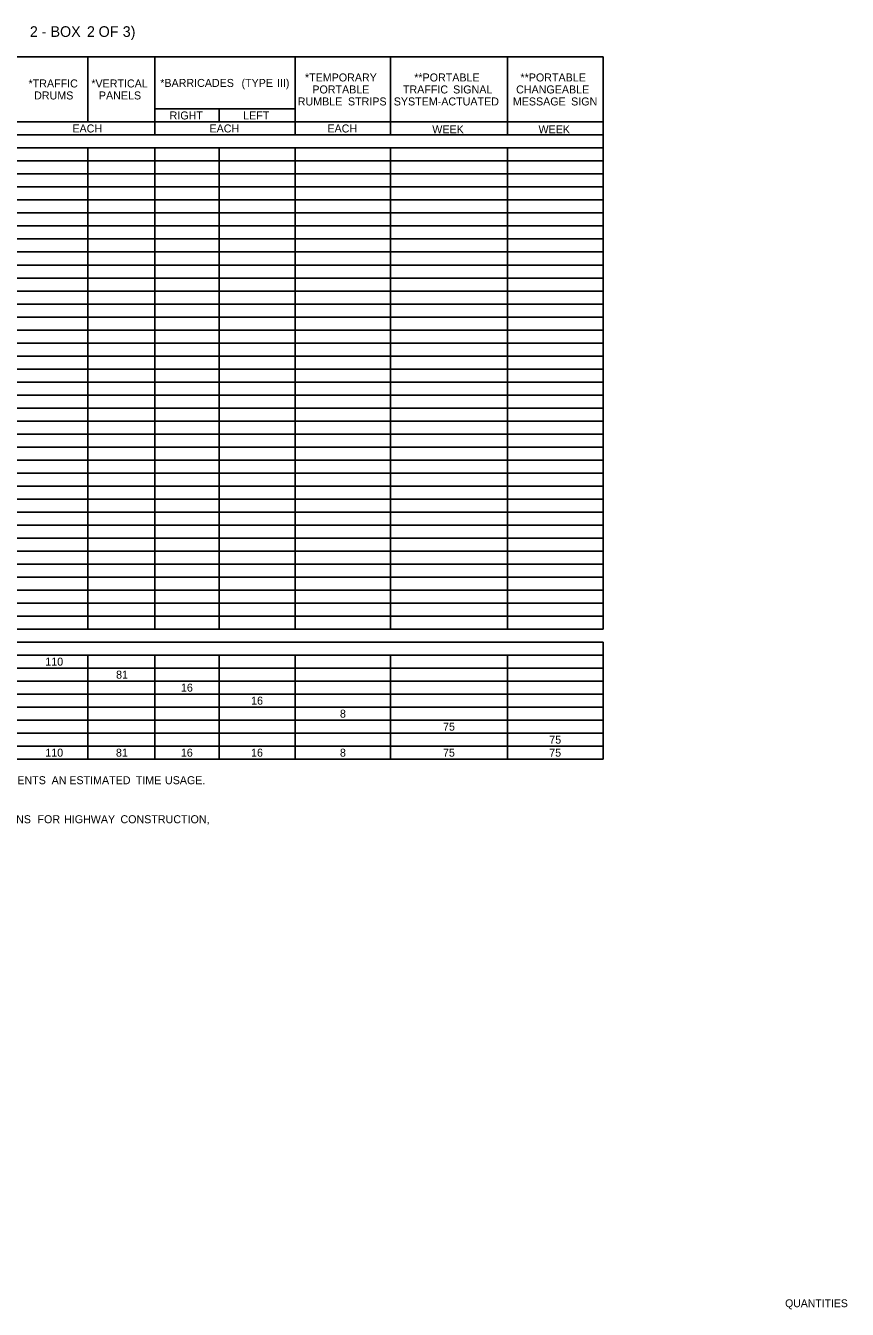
# Model space of a CAD drawing. Extents: x 542596 to 1930787, y -1948294 to 596640.
# Drawn here: x 546993 to 547610, y -1946064 to -1945102 of the extents above; entities that cross this region are included whole.
import ezdxf

# ---------------------------------------------------------------- set-up
doc = ezdxf.new("R2010")
doc.units = 0
doc.layers.add('Default', color=7, linetype='Continuous')
doc.layers.add('R_Border Prem', color=7, linetype='Continuous')

msp = doc.modelspace()

# ---------------------------------------------------------------- linework, layer by layer
at = {"layer": 'Default'}
for p, q in [((546362.8, -1945125.02), (547426.53, -1945125.02)), ((547039.94, -1945173.77), (547039.94, -1945125.02)), ((547090.15, -1945173.77), (547090.15, -1945125.02)), ((547090.15, -1945183.52), (547090.15, -1945125.02)), ((547195.45, -1945183.52), (547195.45, -1945125.02)), ((547267.12, -1945183.52), (547267.12, -1945125.02)), ((547354.87, -1945183.52), (547354.87, -1945125.02)), ((547426.53, -1945554.02), (547426.53, -1945125.02)), ((547090.15, -1945164.02), (547195.45, -1945164.02)), ((547138.42, -1945173.77), (547138.42, -1945164.02)), ((547138.42, -1945173.77), (547138.42, -1945164.02)), ((546889.3, -1945173.77), (547426.53, -1945173.77)), ((547090.15, -1945173.77), (547138.42, -1945173.77)), ((547138.42, -1945173.77), (547426.53, -1945173.77)), ((547195.45, -1945183.52), (547195.45, -1945173.77)), ((547267.12, -1945183.52), (547267.12, -1945173.77)), ((547354.87, -1945183.52), (547354.87, -1945173.77)), ((546362.8, -1945183.52), (547426.53, -1945183.52)), ((546831.29, -1945183.52), (547426.53, -1945183.52)), ((546362.8, -1945193.27), (547426.53, -1945193.27)), ((547039.94, -1945534.52), (547039.94, -1945193.27)), ((547039.94, -1945554.02), (547039.94, -1945193.27)), ((547090.15, -1945534.52), (547090.15, -1945193.27)), ((547090.15, -1945554.02), (547090.15, -1945193.27)), ((547138.42, -1945534.52), (547138.42, -1945193.27)), ((547138.42, -1945554.02), (547138.42, -1945193.27)), ((547195.45, -1945534.52), (547195.45, -1945193.27)), ((547195.45, -1945554.02), (547195.45, -1945193.27)), ((547267.12, -1945554.02), (547267.12, -1945193.27)), ((547354.87, -1945554.02), (547354.87, -1945193.27)), ((546362.8, -1945203.02), (547426.53, -1945203.02)), ((546362.8, -1945212.77), (547426.53, -1945212.77)), ((546362.8, -1945222.52), (547426.53, -1945222.52)), ((546362.8, -1945232.27), (547426.53, -1945232.27)), ((546362.8, -1945242.02), (547426.53, -1945242.02)), ((546362.8, -1945251.77), (547426.53, -1945251.77)), ((546362.8, -1945261.52), (547426.53, -1945261.52)), ((546362.8, -1945271.27), (547426.53, -1945271.27)), ((546362.8, -1945281.02), (547426.53, -1945281.02)), ((546362.8, -1945290.77), (547426.53, -1945290.77)), ((546362.8, -1945300.52), (547426.53, -1945300.52)), ((546362.8, -1945310.27), (547426.53, -1945310.27)), ((546362.8, -1945320.02), (547426.53, -1945320.02)), ((546362.8, -1945329.77), (547426.53, -1945329.77)), ((546362.8, -1945339.52), (547426.53, -1945339.52)), ((546362.8, -1945349.27), (547426.53, -1945349.27)), ((546362.8, -1945359.02), (547426.53, -1945359.02)), ((546362.8, -1945368.77), (547426.53, -1945368.77)), ((546362.8, -1945378.52), (547426.53, -1945378.52)), ((546362.8, -1945388.27), (547426.53, -1945388.27)), ((546362.8, -1945398.02), (547426.53, -1945398.02)), ((546362.8, -1945407.77), (547426.53, -1945407.77)), ((546362.8, -1945417.52), (547426.53, -1945417.52)), ((546362.8, -1945427.27), (547426.53, -1945427.27)), ((546362.8, -1945437.02), (547426.53, -1945437.02)), ((546362.8, -1945446.77), (547426.53, -1945446.77)), ((546362.8, -1945456.52), (547426.53, -1945456.52)), ((546362.8, -1945466.27), (547426.53, -1945466.27)), ((546362.8, -1945476.02), (547426.53, -1945476.02)), ((546362.8, -1945485.77), (547426.53, -1945485.77)), ((546362.8, -1945495.52), (547426.53, -1945495.52)), ((546362.8, -1945505.27), (547426.53, -1945505.27)), ((546362.8, -1945515.02), (547426.53, -1945515.02)), ((546362.8, -1945524.77), (547426.53, -1945524.77)), ((546362.8, -1945534.52), (547426.53, -1945534.52)), ((546362.8, -1945544.27), (547426.53, -1945544.27)), ((547039.94, -1945554.02), (547039.94, -1945544.27)), ((547090.15, -1945554.02), (547090.15, -1945544.27)), ((547138.42, -1945554.02), (547138.42, -1945544.27)), ((547195.45, -1945554.02), (547195.45, -1945544.27)), ((547267.12, -1945554.02), (547267.12, -1945544.27)), ((546362.8, -1945554.02), (547426.53, -1945554.02)), ((546362.8, -1945563.77), (547426.53, -1945563.77)), ((546413.02, -1945563.77), (547267.12, -1945563.77)), ((547267.12, -1945563.77), (547426.53, -1945563.77)), ((547426.53, -1945651.52), (547426.53, -1945563.77)), ((546362.8, -1945573.52), (547426.53, -1945573.52)), ((547039.94, -1945651.52), (547039.94, -1945573.52)), ((547039.94, -1945651.52), (547039.94, -1945573.52)), ((547090.15, -1945651.52), (547090.15, -1945573.52)), ((547090.15, -1945651.52), (547090.15, -1945573.52)), ((547138.42, -1945593.02), (547138.42, -1945573.52)), ((547138.42, -1945651.52), (547138.42, -1945573.52)), ((547195.45, -1945612.52), (547195.45, -1945573.52)), ((547195.45, -1945651.52), (547195.45, -1945573.52)), ((547267.12, -1945651.52), (547267.12, -1945573.52)), ((547354.87, -1945651.52), (547354.87, -1945573.52)), ((546362.8, -1945583.27), (547426.53, -1945583.27)), ((546362.8, -1945593.02), (547426.53, -1945593.02)), ((546362.8, -1945602.77), (547426.53, -1945602.77)), ((547138.42, -1945651.52), (547138.42, -1945602.77)), ((546362.8, -1945612.52), (547426.53, -1945612.52)), ((546362.8, -1945622.27), (547426.53, -1945622.27)), ((547195.45, -1945651.52), (547195.45, -1945622.27)), ((546362.8, -1945632.02), (547426.53, -1945632.02)), ((546680.65, -1945632.02), (547426.53, -1945632.02)), ((546362.8, -1945641.77), (547426.53, -1945641.77)), ((547267.12, -1945651.52), (547267.12, -1945641.77)), ((546362.8, -1945651.52), (547426.53, -1945651.52))]:
    msp.add_line(p, q, dxfattribs=at)

# ---------------------------------------------------------------- texts
for s, height, p in [(' 2', 8, (546993.51, -1945110.01)), (' BOX', 8, (547009.01, -1945110.01)), (' 2', 8, (547036.32, -1945110.01)), (' OF', 8, (547045.08, -1945110.01)), (' 3)', 8, (547063.19, -1945110.01)), (' -', 8, (547002.26, -1945110.01)), ('*TRAFFIC', 6, (546995.49, -1945147.9)), ('*VERTICAL', 6, (547042.58, -1945147.9)), ('*BARRICADES', 6, (547094.3, -1945147.52)), (' (TYPE', 6, (547153.04, -1945147.52)), (' III)', 6, (547179.64, -1945147.52)), ('*TEMPORARY', 6, (547202.86, -1945143.4)), ('**PORTABLE', 6, (547284.88, -1945143.4)), ('**PORTABLE', 6, (547364.59, -1945143.4)), ('DRUMS', 6, (546999.67, -1945156.9)), ('PANELS', 6, (547048.25, -1945156.9)), ('PORTABLE', 6, (547208.43, -1945152.4)), ('TRAFFIC', 6, (547276.4, -1945152.4)), (' SIGNAL', 6, (547311.83, -1945152.4)), ('CHANGEABLE', 6, (547361.33, -1945152.4)), ('RUMBLE', 6, (547197.46, -1945161.4)), (' STRIPS', 6, (547232.91, -1945161.4)), ('SYSTEM-ACTUATED', 6, (547269.51, -1945161.4)), ('MESSAGE', 6, (547358.86, -1945161.4)), (' SIGN', 6, (547400.38, -1945161.4)), ('RIGHT', 6, (547101.33, -1945171.9)), ('LEFT', 6, (547156.54, -1945171.9)), ('EACH', 6, (547028.38, -1945181.65)), ('EACH', 6, (547131.25, -1945181.65)), ('EACH', 6, (547219.73, -1945181.65)), ('WEEK', 6, (547298.42, -1945182.32)), ('WEEK', 6, (547378.13, -1945182.32)), ('110', 6, (547008.05, -1945581.4)), ('81', 6, (547061.16, -1945591.15)), ('16', 6, (547109.81, -1945600.9)), ('16', 6, (547162.46, -1945610.65)), ('8', 6, (547229.14, -1945620.4)), ('75', 6, (547306.5, -1945630.15)), ('75', 6, (547386.2, -1945639.9)), ('110', 6, (547008.05, -1945649.65)), ('81', 6, (547061.07, -1945649.65)), ('16', 6, (547109.77, -1945649.65)), ('16', 6, (547162.42, -1945649.65)), ('8', 6, (547229.14, -1945649.65)), ('75', 6, (547306.46, -1945649.65)), ('75', 6, (547386.16, -1945649.65)), (' REPRESENTS', 6, (546951.82, -1945670.31)), (' AN', 6, (547010.55, -1945670.31)), (' ESTIMATED', 6, (547023.84, -1945670.31)), (' TIME', 6, (547073.7, -1945670.31)), (' USAGE.', 6, (547095.61, -1945670.31)), (' SPECIFICATIONS', 6, (546928.2, -1945699.56)), (' FOR', 6, (546999.97, -1945699.56)), (' HIGHWAY', 6, (547019.88, -1945699.56)), (' CONSTRUCTION,', 6, (547062.2, -1945699.56))]:
    msp.add_text(s, height=height, dxfattribs=at).set_placement(p)
at = {"layer": 'R_Border Prem'}
msp.add_text('QUANTITIES', height=5.862, rotation=360, dxfattribs=at).set_placement((547563.18, -1946062.39))

doc.saveas('drawing.dxf')
